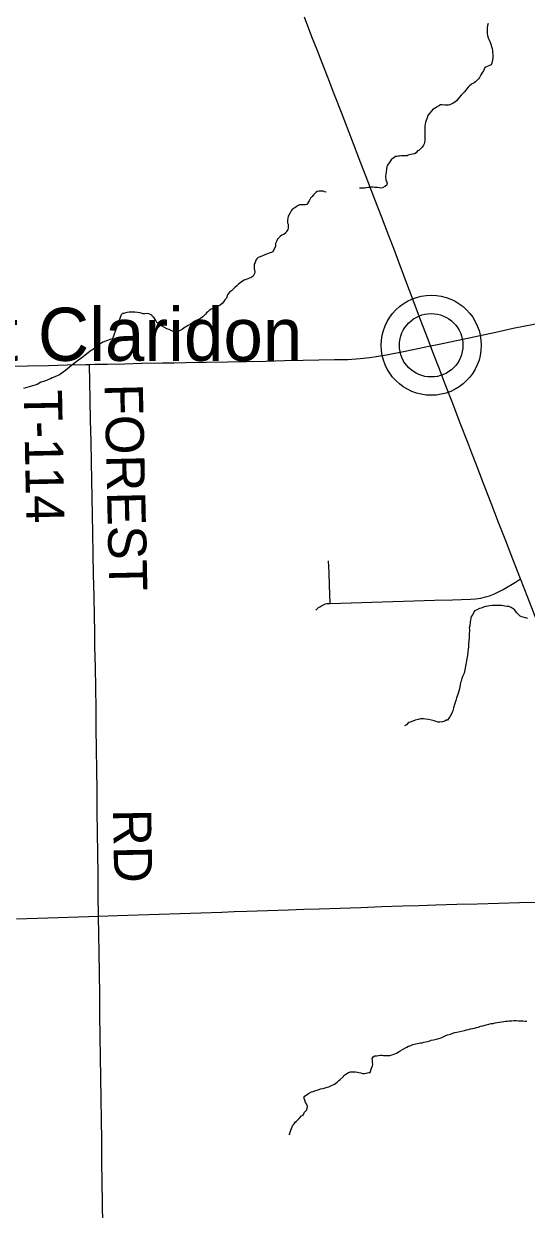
# Model space of a CAD drawing. Extents: x 103424 to 290657, y 38711 to 110967.
# Drawn here: x 166271 to 170241, y 76839 to 86206 of the extents above; entities that cross this region are included whole.
import ezdxf

# ---------------------------------------------------------------- set-up
doc = ezdxf.new("R2010")
doc.units = 0
for name, color, linetype in [('GM_X_Minor_River', 7, 'Continuous'), ('GM_X_State_Route', 7, 'Continuous'), ('GM_X_Township_Road', 7, 'Continuous'), ('GM_X_Township_Road_Text', 7, 'Continuous'), ('GM_X_Unincorporated', 7, 'Continuous'), ('GM_X_Unincorporated_Location', 7, 'Continuous'), ('GM_X_Unincorporated_Text', 7, 'Continuous'), ('GM_X_US_Route', 7, 'Continuous')]:
    doc.layers.add(name, color=color, linetype=linetype)

msp = doc.modelspace()

# ---------------------------------------------------------------- linework, layer by layer
at = {"layer": 'GM_X_Minor_River'}
for points in [[(169938.6, 86206.4), (169934.6, 86192.3), (169932.7, 86174.1), (169930.8, 86159.9), (169930.9, 86145.7), (169931, 86127.5), (169933.1, 86113.4), (169939.2, 86095.2), (169945.4, 86083.1), (169951.5, 86069), (169955.6, 86058.9), (169959.8, 86044.8), (169965.9, 86026.6), (169970.1, 86010.4), (169974.2, 85994.3), (169974.3, 85976.1), (169976.4, 85964), (169976.5, 85953.8), (169976.6, 85939.7), (169974.7, 85919.5), (169968.8, 85893.1), (169962.8, 85881), (169912.4, 85858.5), (169902.5, 85832.1), (169890.5, 85813.9), (169882.5, 85801.7), (169876.5, 85791.6), (169872.5, 85781.4), (169862.5, 85769.3), (169852.4, 85759.1), (169840.4, 85746.9), (169828.3, 85738.7), (169818.2, 85732.6), (169808.2, 85728.5), (169792.1, 85714.3), (169782, 85704.1), (169772, 85692), (169762, 85679.8), (169750, 85665.5), (169737.9, 85651.3), (169725.9, 85641.2), (169711.8, 85622.9), (169699.8, 85608.7), (169689.8, 85596.5), (169675.7, 85586.3), (169663.6, 85578.2), (169651.5, 85572), (169637.4, 85565.9), (169625.4, 85561.8)], [(169625.4, 85561.8), (169613.2, 85561.7), (169597.1, 85561.7), (169576.9, 85563.6), (169562.7, 85563.5), (169550.6, 85557.4), (169532.5, 85545.2), (169520.5, 85537), (169510.4, 85532.9), (169500.3, 85524.8), (169472.3, 85492.3), (169464.2, 85480.1), (169458.3, 85461.9), (169450.3, 85439.6), (169444.4, 85425.4), (169442.4, 85413.3), (169440.5, 85393), (169438.7, 85370.8), (169438.7, 85354.6), (169438.8, 85338.4), (169439, 85306.1), (169439.2, 85281.8), (169437.3, 85267.6), (169433.3, 85257.5), (169429.3, 85245.4), (169417.3, 85231.1), (169409.3, 85221), (169391.2, 85204.7), (169381.1, 85200.6), (169371.1, 85186.4), (169357, 85178.3), (169342.9, 85174.1), (169328.8, 85172), (169308.6, 85165.9), (169298.5, 85161.8), (169288.4, 85161.7), (169278.3, 85161.7), (169262.2, 85161.6), (169252.1, 85161.6), (169240, 85159.5), (169229.9, 85159.4), (169217.7, 85157.3), (169207.7, 85155.3), (169197.6, 85149.2), (169185.5, 85141), (169175.5, 85134.9), (169167.5, 85122.7), (169157.5, 85106.5), (169145.4, 85088.2), (169139.5, 85076.1), (169135.5, 85059.9), (169133.7, 85033.6), (169129.8, 85001.2), (169132, 84972.9), (169138.2, 84954.7), (169142.3, 84944.6), (169136.3, 84928.4), (169122.2, 84918.2), (169106.1, 84910.1), (169092, 84906), (169065.7, 84911.9), (169043.5, 84911.8), (169027.3, 84913.7), (169015.2, 84913.7), (169005.1, 84911.6), (168995, 84911.5), (168978.9, 84909.4), (168964.7, 84907.3), (168950.6, 84907.3), (168938.5, 84907.2), (168928.4, 84905.1), (168924.3, 84905.1)], [(168659.9, 84875.5), (168645.7, 84877.5), (168635.6, 84881.5), (168619.4, 84883.4), (168601.3, 84883.3), (168589.2, 84879.2), (168579.1, 84873.1), (168569.1, 84864.9), (168559, 84852.8), (168549, 84840.6), (168537, 84826.4), (168525, 84806.1), (168507, 84777.7), (168496.9, 84773.6), (168482.7, 84773.5), (168464.6, 84773.4), (168448.4, 84773.3), (168434.3, 84767.2), (168420.2, 84757), (168406.1, 84748.9), (168392.1, 84736.7), (168384.1, 84726.5), (168376.1, 84710.3), (168366.1, 84694.1), (168360.1, 84683.9), (168356.1, 84669.8), (168354.2, 84649.5), (168354.3, 84633.3), (168358.4, 84621.2), (168360.5, 84607.1), (168358.6, 84590.9), (168356.7, 84580.8), (168346.7, 84564.6), (168340.7, 84554.4), (168324.6, 84540.2), (168308.5, 84534), (168296.4, 84523.9), (168286.4, 84513.7), (168276.3, 84503.5), (168270.3, 84491.4), (168264.4, 84479.2), (168260.4, 84469.1), (168260.5, 84456.9), (168258.5, 84444.8), (168244.5, 84416.4), (168238.6, 84404.2), (168226.5, 84398.1), (168210.3, 84394), (168188.2, 84385.8), (168174.1, 84379.7), (168155.9, 84371.5), (168137.8, 84363.3), (168123.7, 84357.2), (168111.6, 84349), (168103.6, 84336.9), (168097.7, 84318.6), (168091.7, 84306.5), (168089.8, 84290.3), (168089.8, 84280.2), (168091.9, 84270.1), (168094, 84260), (168096.1, 84245.8), (168094.2, 84231.6), (168084.2, 84211.4), (168068.1, 84201.2), (168054, 84195), (168041.9, 84190.9), (168027.8, 84184.8), (168011.7, 84178.7), (167999.6, 84172.5), (167989.5, 84164.4), (167977.5, 84156.2), (167965.4, 84146.1), (167953.3, 84133.9), (167939.3, 84121.7), (167925.2, 84109.5), (167911.2, 84095.2), (167897.1, 84085.1), (167889.1, 84074.9), (167881.1, 84062.7), (167873.1, 84038.4), (167859.1, 84024.2), (167851.1, 84012), (167839, 83995.8), (167823, 83981.6), (167806.9, 83973.4), (167790.7, 83967.2), (167776.6, 83963.1), (167766.6, 83957), (167750.4, 83950.9), (167734.3, 83938.7), (167724.3, 83928.5), (167714.3, 83920.3), (167706.2, 83910.2), (167696.2, 83900), (167686.2, 83889.9), (167668.1, 83877.7), (167652, 83867.5), (167637.8, 83863.3), (167617.7, 83853.1), (167603.6, 83842.9)], [(167603.6, 83842.9), (167587.5, 83832.8), (167569.4, 83820.5), (167555.3, 83812.4), (167545.3, 83808.3), (167525.2, 83792), (167501, 83779.8), (167476.8, 83771.5), (167460.7, 83769.5), (167440.4, 83779.5), (167420.1, 83789.5), (167401.9, 83795.4), (167365.4, 83815.5), (167353.2, 83825.5), (167335, 83839.6), (167322.8, 83845.6), (167314.7, 83859.7), (167308.5, 83869.8), (167300.4, 83881.9), (167288.2, 83892), (167282.1, 83902), (167272, 83908.1), (167257.8, 83914), (167241.6, 83916), (167227.5, 83913.9), (167215.4, 83913.8), (167199.2, 83919.8), (167187, 83921.8), (167168.8, 83923.7), (167148.6, 83925.6), (167130.4, 83925.6), (167118.3, 83927.5), (167104.2, 83925.4), (167088, 83923.3), (167073.9, 83921.2), (167061.8, 83917.1), (167051.7, 83915.1), (167039.7, 83904.9), (166971.2, 83716)], [(166952.7, 83709.7), (166896.5, 83688.3), (166880.5, 83680), (166864.6, 83667.6), (166844.6, 83653.1), (166820.7, 83634.5), (166794.8, 83617.8), (166767, 83595.1), (166733.2, 83568.2), (166693.3, 83539.2), (166647.5, 83504.1), (166599.8, 83464.9), (166552, 83431.7), (166515.9, 83414.9), (166495.9, 83408.4), (166481.9, 83400.1), (166465.9, 83393.8), (166449.8, 83387.4), (166433.8, 83381.1), (166417.7, 83376.7), (166405.7, 83372.5), (166377.8, 83353.8), (166321.6, 83338.7), (166287.5, 83327.9), (166269.4, 83323.6)], [(166971.2, 83716), (166952.7, 83709.7)], [(170254, 81506.2), (170233.8, 81512.1), (170223.7, 81514.1), (170205.5, 81520.1), (170191.3, 81526.1), (170175, 81542.2), (170166.9, 81552.2), (170156.7, 81564.3), (170146.5, 81576.4), (170136.4, 81582.4), (170122.2, 81594.5), (170101.9, 81600.4), (170089.8, 81602.4), (170071.6, 81604.3), (170059.5, 81606.3), (170045.3, 81608.2), (170035.2, 81608.2), (170019.1, 81610.1), (170002.9, 81610.1), (169986.7, 81610), (169970.6, 81607.9), (169952.4, 81605.8), (169920.1, 81601.6), (169908, 81597.5), (169898, 81593.4), (169883.8, 81589.3), (169871.8, 81585.2), (169855.6, 81577), (169845.6, 81572.9), (169831.5, 81566.7), (169819.5, 81538.4), (169805.5, 81522.1), (169797.7, 81479.6), (169793.8, 81449.3), (169789.9, 81433.1), (169791.9, 81421), (169792, 81408.8), (169790.1, 81384.5), (169788.3, 81356.2), (169786.5, 81327.9), (169784.6, 81307.7), (169784.6, 81297.5), (169784.7, 81283.4), (169782.8, 81263.2), (169778.9, 81242.9), (169777, 81214.6), (169771.1, 81190.3), (169767.2, 81170.1), (169765.3, 81157.9), (169763.3, 81143.8), (169749.6, 81074.9), (169739.6, 81052.6), (169731.7, 81032.4), (169725.8, 81012.1), (169719.8, 81002), (169712, 80949.4), (169700.1, 80904.8), (169688.2, 80880.5), (169684.3, 80858.2), (169674.4, 80825.8), (169666.4, 80801.5), (169658.5, 80769.1), (169638.6, 80734.6), (169618.5, 80704.2), (169608.5, 80702.1), (169596.4, 80694), (169578.2, 80689.8), (169558, 80687.7), (169543.9, 80687.6), (169529.7, 80691.6), (169513.5, 80697.6), (169491.3, 80703.6), (169467, 80707.5), (169444.8, 80711.4), (169428.6, 80713.4), (169418.5, 80713.3), (169406.4, 80713.3), (169386.2, 80709.1), (169364, 80702.9), (169343.9, 80694.7), (169323.7, 80688.6), (169309.6, 80684.5), (169293.5, 80666.2), (169279.4, 80658)], [(169619.5, 78216.8), (169641.7, 78223), (169659.8, 78229.1), (169676, 78235.3), (169692.1, 78239.4), (169738.5, 78247.7), (169752.6, 78251.8), (169768.8, 78255.9), (169784.9, 78260.1), (169799, 78264.2), (169815.2, 78268.3), (169831.3, 78270.4), (169847.4, 78274.5), (169863.6, 78278.7), (169879.7, 78284.8), (169897.9, 78288.9), (169924.1, 78295.1), (169944.2, 78301.3), (169962.4, 78305.4), (169978.5, 78307.5), (169994.7, 78311.7), (170010.8, 78313.7), (170029, 78317.9), (170047.1, 78320), (170063.3, 78322.1), (170077.4, 78324.2), (170089.5, 78326.3), (170103.7, 78328.4), (170125.9, 78328.5), (170142, 78330.6), (170160.2, 78330.7), (170178.4, 78328.7), (170196.6, 78326.8), (170214.8, 78326.9), (170228.9, 78324.9), (170245.1, 78325)], [(168367.8, 77425.9), (168371.8, 77436.1), (168375.8, 77448.2), (168381.8, 77464.4), (168385.7, 77476.6), (168397.7, 77502.9), (168407.7, 77515.1), (168415.7, 77527.3), (168425.8, 77535.4), (168435.8, 77545.6), (168445.9, 77555.7), (168465.9, 77576.1), (168478, 77582.2), (168490, 77606.5), (168506, 77624.8), (168511.9, 77651.1), (168505.7, 77671.3), (168497.6, 77683.4), (168491.4, 77699.6), (168487.3, 77713.7), (168487.2, 77729.9), (168519.4, 77752.3), (168543.5, 77766.6), (168557.7, 77770.7), (168575.8, 77776.8), (168596, 77783), (168616.1, 77789.2), (168636.3, 77793.3), (168652.4, 77797.4), (168666.5, 77803.6), (168680.7, 77805.7), (168692.8, 77811.8), (168702.8, 77815.9), (168714.9, 77822), (168725, 77826.1), (168735, 77834.2), (168747.1, 77844.4), (168759.1, 77856.6), (168771.2, 77864.7), (168793.3, 77885.1), (168799.3, 77895.2), (168815.4, 77907.4), (168835.5, 77919.7), (168851.7, 77923.8), (168863.8, 77925.9), (168875.9, 77925.9), (168892.1, 77924), (168906.2, 77922), (168918.4, 77920.1), (168934.5, 77916.1), (168946.7, 77912.1), (168958.8, 77912.2), (168974.9, 77914.3), (168997.1, 77918.4), (169007.2, 77920.5), (169017.1, 77955), (169027.1, 77973.2), (169029.1, 77983.3), (169026.9, 78001.5), (169024.8, 78015.6), (169022.7, 78029.8), (169030.7, 78044), (169044.8, 78050.1), (169058.9, 78052.2), (169073.1, 78054.3), (169089.2, 78056.4), (169101.3, 78056.5), (169113.5, 78054.5), (169131.7, 78054.6), (169151.9, 78052.7), (169162, 78054.8), (169172, 78056.8), (169188.2, 78061), (169202.3, 78067.1), (169214.4, 78071.2), (169228.5, 78079.3), (169244.6, 78091.6), (169262.7, 78101.8), (169280.8, 78112), (169296.9, 78120.1), (169311, 78126.3), (169323.1, 78130.4), (169333.2, 78134.5), (169345.3, 78140.6), (169367.5, 78144.7), (169381.6, 78148.9), (169393.7, 78150.9), (169405.8, 78153), (169417.9, 78155.1), (169432, 78159.2), (169446.1, 78161.3), (169460.2, 78165.4), (169474.4, 78167.5), (169488.5, 78173.7), (169506.6, 78177.8), (169530.8, 78184), (169549, 78188.1), (169567.1, 78194.3), (169583.3, 78200.4), (169599.4, 78208.6), (169619.5, 78216.8)]]:
    msp.add_lwpolyline(points, dxfattribs=at)
at = {"layer": 'GM_X_State_Route'}
for points in [[(168692, 85731.9), (168674.6, 85776.6), (168628, 85895.6), (168588, 85998.8), (168547.9, 86102), (168488.4, 86256)], [(169483.9, 83660.1), (169464.4, 83711.5), (169406.2, 83866), (169348, 84020.4), (169289.8, 84174.9), (169231.6, 84329.4), (169193.9, 84429.5), (169156.2, 84529.5), (169096.4, 84683.4), (169044.8, 84816), (168993.2, 84948.6), (168934.3, 85102.8), (168875.4, 85257), (168828.3, 85380.4), (168781.2, 85503.8), (168721.1, 85657.5), (168692, 85731.9)], [(170521.9, 80978.8), (170490.1, 81060.6), (170430.5, 81214.5), (170370.8, 81368.4), (170340.9, 81445.5), (170311.1, 81522.5), (170252.9, 81671.5), (170194.7, 81820.6), (170135, 81974.4), (170078.6, 82119.6), (170022.3, 82264.8), (169962.8, 82418.8), (169903.2, 82572.8), (169843.7, 82726.8), (169810.9, 82811.6), (169778.1, 82896.4), (169718.7, 83050.5), (169659.4, 83204.5), (169600, 83358.5), (169551.6, 83484), (169503.2, 83609.5), (169483.9, 83660.1)]]:
    msp.add_lwpolyline(points, dxfattribs=at)
at = {"layer": 'GM_X_Township_Road'}
for points in [[(166895.8, 76721.7), (166893.5, 76886.8), (166891.2, 77051.9), (166888.9, 77216.9), (166886.6, 77382), (166884.3, 77547.1), (166882, 77712.1), (166879.7, 77877.2), (166877.4, 78042.2), (166875.2, 78207.3), (166872.8, 78372.4), (166870.6, 78537.4), (166868.3, 78702.5), (166866, 78867.6), (166864, 79011), (166862, 79154.5), (166860, 79319.6), (166858, 79484.7), (166855.9, 79649.7), (166853.9, 79814.8), (166851.9, 79979.8), (166849.9, 80144.9), (166847.9, 80310), (166845.9, 80475), (166843.9, 80640.1), (166842, 80798.1), (166840.1, 80956.2), (166836.8, 81121.2), (166833.5, 81286.2), (166831.2, 81403.6), (166828.8, 81521), (166825.9, 81686), (166822.9, 81851.1), (166819.9, 82016.1), (166816.9, 82181.1), (166814.4, 82322.1), (166811.8, 82463.1), (166809, 82601.7), (166806.2, 82740.4), (166802.7, 82905.4), (166799.2, 83070.4), (166795.7, 83235.5), (166792.7, 83374.3), (166789.7, 83513.1)], [(168691.8, 81625.8), (168687.3, 81770.8), (168683.5, 81866.4), (168679.6, 81962)], [(168578.6, 81571.8), (168589.7, 81583.9), (168600.4, 81592.9), (168610.4, 81599.6), (168623.9, 81607.1), (168642.9, 81617.2), (168653.9, 81622.5), (168666, 81624.9), (168691.8, 81625.8), (168856.8, 81630.7), (169021.8, 81635.6), (169186.8, 81640.6), (169351.8, 81645.5), (169516.8, 81650.4), (169659, 81654.6), (169801.3, 81658.9), (169840.3, 81661.5), (169881.9, 81667.8), (169919.2, 81678.4), (169950.9, 81686.3), (169989.8, 81702.1), (170022, 81716.8), (170057.8, 81734.7), (170154.7, 81794.7), (170194.7, 81820.6)], [(166213.8, 79132.7), (166378.7, 79138.2), (166543.7, 79143.8), (166702.9, 79149.1), (166862, 79154.5), (167011, 79159.5), (167176, 79165.1), (167340.9, 79170.6), (167505.9, 79176.1), (167670.9, 79181.7), (167835.8, 79187.3), (167934, 79190.6), (168032.3, 79193.9), (168197.3, 79199.5), (168362.2, 79205), (168483.6, 79209.1), (168605, 79213.2), (168769.9, 79218.7), (168934.9, 79224.2), (169099.9, 79229.8), (169264.8, 79235.3), (169395.5, 79239.7), (169526.1, 79244.1), (169691.1, 79248.5), (169856.1, 79253), (170021.1, 79257.4), (170186.1, 79261.8), (170351.1, 79266.2)]]:
    msp.add_lwpolyline(points, dxfattribs=at)
at = {"layer": 'GM_X_Unincorporated'}
for radius in [395.3, 250.6]:
    msp.add_circle((169489.8, 83665), radius, dxfattribs=at)
at = {"layer": 'GM_X_Unincorporated_Location'}
msp.add_line((169489.8, 83665), (169489.8, 83665), dxfattribs=at)
at = {"layer": 'GM_X_US_Route'}
for points in [[(169483.9, 83660.1), (169540, 83671.9), (169701.5, 83706.2), (169862.9, 83740.5), (170000.6, 83769.7), (170138.3, 83798.9), (170300.1, 83831.4), (170381.3, 83847.7), (170462.6, 83864), (170609.6, 83894.6), (170771.3, 83927.4), (170930.1, 83959.5), (171088.9, 83991.7), (171250.9, 84023.5), (171347.6, 84042.6), (171444.3, 84061.6), (171606.1, 84094.3), (171767.9, 84127), (171830.2, 84139.6)], [(166895.9, 83515.9), (166932.8, 83516.8), (167067.2, 83519.6), (167201.6, 83522.4), (167366.6, 83525.5), (167458.6, 83527.2), (167550.5, 83528.9), (167715.6, 83531.9), (167880.6, 83534.9), (168031.5, 83537.6), (168182.5, 83540.3), (168330, 83543.4), (168477.6, 83546.5), (168602.2, 83549.2), (168726.9, 83551.9), (168831.4, 83552.7), (168929.1, 83561.2), (169005.3, 83567.7), (169135.3, 83589.3), (169284, 83618.6), (169384, 83639.4), (169483.9, 83660.1)], [(166135.9, 83499), (166300.9, 83502.6), (166465.9, 83506.1), (166613.7, 83509.3), (166761.4, 83512.5), (166789.7, 83513.1), (166832.8, 83514.5), (166895.9, 83515.9)]]:
    msp.add_lwpolyline(points, dxfattribs=at)

# ---------------------------------------------------------------- texts
at = {"layer": 'GM_X_Township_Road_Text'}
for s, rotation, p in [('T-114', 271.12227, (166271.1, 83309.4)), ('FOREST', 271.29369, (166909.3, 83358.7)), ('RD', 270.99026, (166975.7, 79998.8))]:
    msp.add_text(s, height=301.87, rotation=rotation, dxfattribs=at).set_placement(p)
at = {"layer": 'GM_X_Unincorporated_Text'}
msp.add_text('East Claridon', height=419.602, rotation=0.00001, dxfattribs=at).set_placement((165103.7, 83541.9))

doc.saveas('drawing.dxf')
